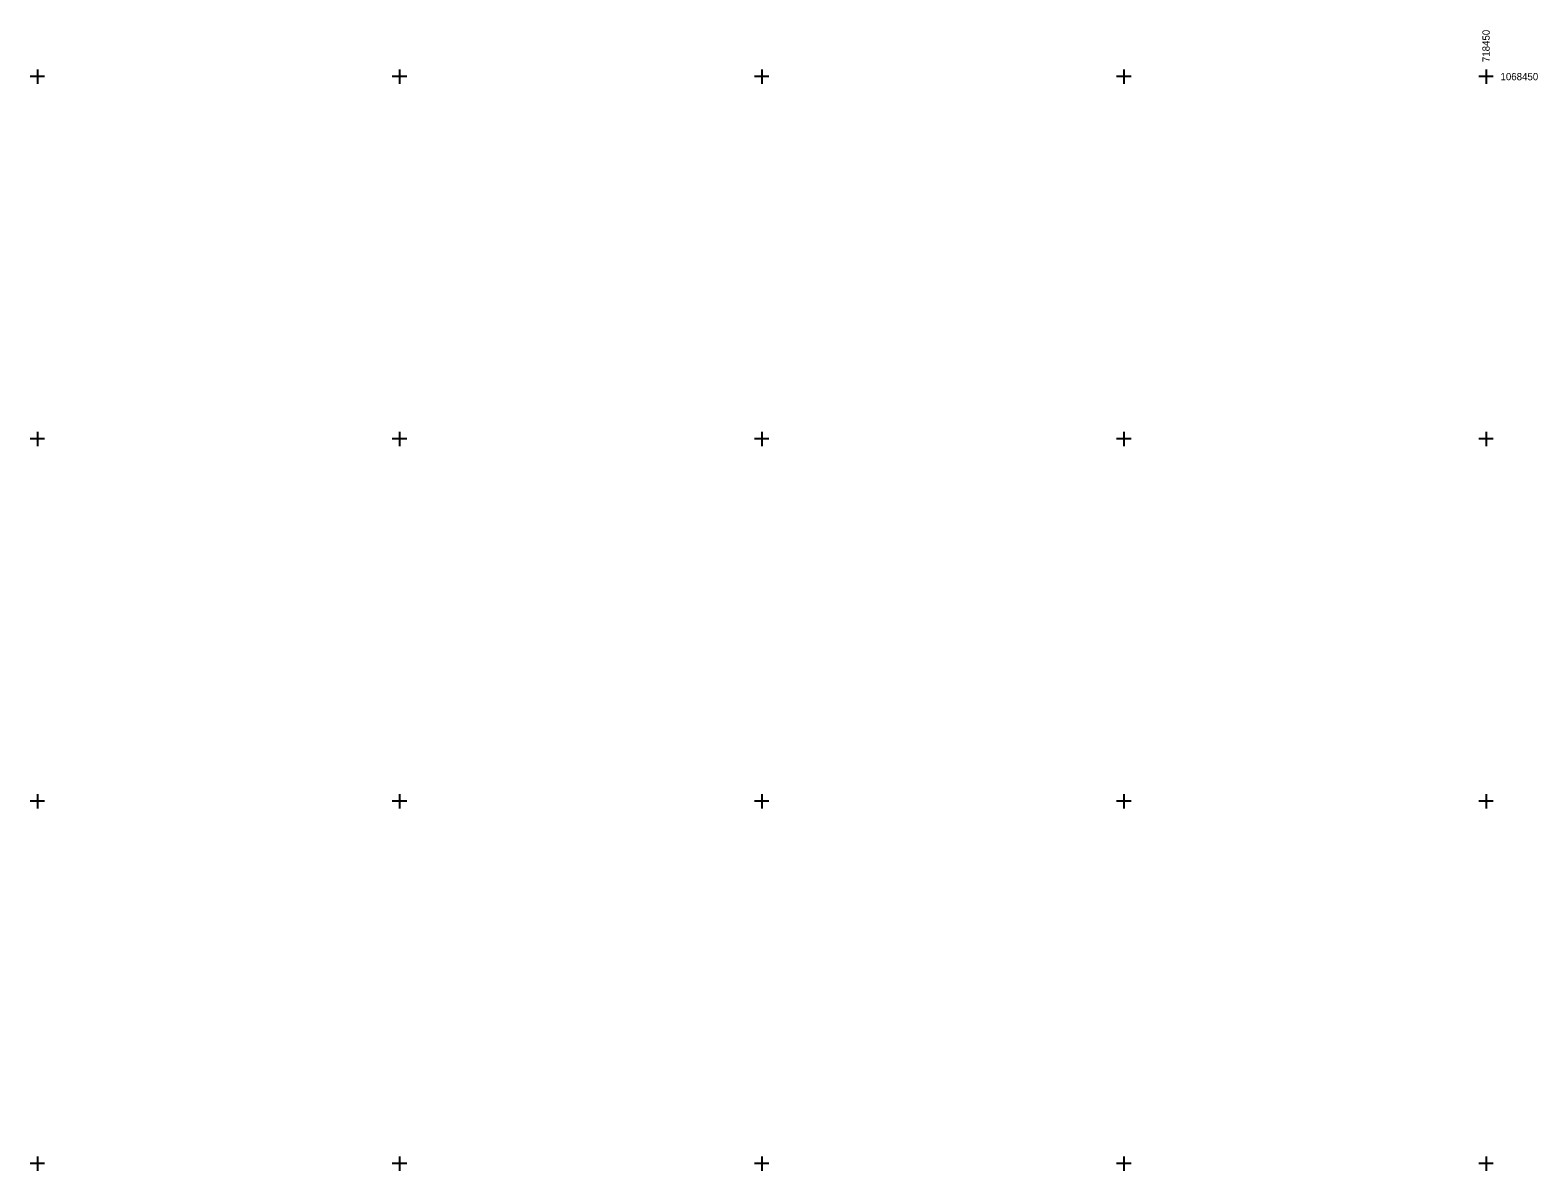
# Model space of a CAD drawing. Extents: x -718951 to -718443, y -1070201 to -1068444.
# Drawn here: x -718651 to -718442.8, y -1068601 to -1068443.6 of the extents above; entities that cross this region are included whole.
import ezdxf

# ---------------------------------------------------------------- set-up
doc = ezdxf.new("R2010")
doc.units = 0
doc.layers.add('GEO_Hektarová síť', color=7, linetype='Continuous')

msp = doc.modelspace()

# ---------------------------------------------------------------- linework, layer by layer
at = {"layer": 'GEO_Hektarová síť'}
for points in [[(-718649, -1068450), (-718650, -1068450), (-718651, -1068450)], [(-718650, -1068449), (-718650, -1068450), (-718650, -1068451)], [(-718599, -1068450), (-718600, -1068450), (-718601, -1068450)], [(-718600, -1068449), (-718600, -1068450), (-718600, -1068451)], [(-718549, -1068450), (-718550, -1068450), (-718551, -1068450)], [(-718550, -1068449), (-718550, -1068450), (-718550, -1068451)], [(-718499, -1068450), (-718500, -1068450), (-718501, -1068450)], [(-718500, -1068449), (-718500, -1068450), (-718500, -1068451)], [(-718449, -1068450), (-718450, -1068450), (-718451, -1068450)], [(-718450, -1068449), (-718450, -1068450), (-718450, -1068451)], [(-718649, -1068500), (-718650, -1068500), (-718651, -1068500)], [(-718650, -1068499), (-718650, -1068500), (-718650, -1068501)], [(-718599, -1068500), (-718600, -1068500), (-718601, -1068500)], [(-718600, -1068499), (-718600, -1068500), (-718600, -1068501)], [(-718549, -1068500), (-718550, -1068500), (-718551, -1068500)], [(-718550, -1068499), (-718550, -1068500), (-718550, -1068501)], [(-718499, -1068500), (-718500, -1068500), (-718501, -1068500)], [(-718500, -1068499), (-718500, -1068500), (-718500, -1068501)], [(-718449, -1068500), (-718450, -1068500), (-718451, -1068500)], [(-718450, -1068499), (-718450, -1068500), (-718450, -1068501)], [(-718649, -1068550), (-718650, -1068550), (-718651, -1068550)], [(-718650, -1068549), (-718650, -1068550), (-718650, -1068551)], [(-718599, -1068550), (-718600, -1068550), (-718601, -1068550)], [(-718600, -1068549), (-718600, -1068550), (-718600, -1068551)], [(-718549, -1068550), (-718550, -1068550), (-718551, -1068550)], [(-718550, -1068549), (-718550, -1068550), (-718550, -1068551)], [(-718499, -1068550), (-718500, -1068550), (-718501, -1068550)], [(-718500, -1068549), (-718500, -1068550), (-718500, -1068551)], [(-718449, -1068550), (-718450, -1068550), (-718451, -1068550)], [(-718450, -1068549), (-718450, -1068550), (-718450, -1068551)], [(-718649, -1068600), (-718650, -1068600), (-718651, -1068600)], [(-718650, -1068599), (-718650, -1068600), (-718650, -1068601)], [(-718599, -1068600), (-718600, -1068600), (-718601, -1068600)], [(-718600, -1068599), (-718600, -1068600), (-718600, -1068601)], [(-718549, -1068600), (-718550, -1068600), (-718551, -1068600)], [(-718550, -1068599), (-718550, -1068600), (-718550, -1068601)], [(-718499, -1068600), (-718500, -1068600), (-718501, -1068600)], [(-718500, -1068599), (-718500, -1068600), (-718500, -1068601)], [(-718449, -1068600), (-718450, -1068600), (-718451, -1068600)], [(-718450, -1068599), (-718450, -1068600), (-718450, -1068601)]]:
    msp.add_lwpolyline(points, dxfattribs=at)

# ---------------------------------------------------------------- texts
msp.add_text('718450', height=1, rotation=90, dxfattribs=at).set_placement((-718449.5, -1068448))
msp.add_text('1068450', height=1, dxfattribs=at).set_placement((-718448, -1068450.5))

doc.saveas('drawing.dxf')
